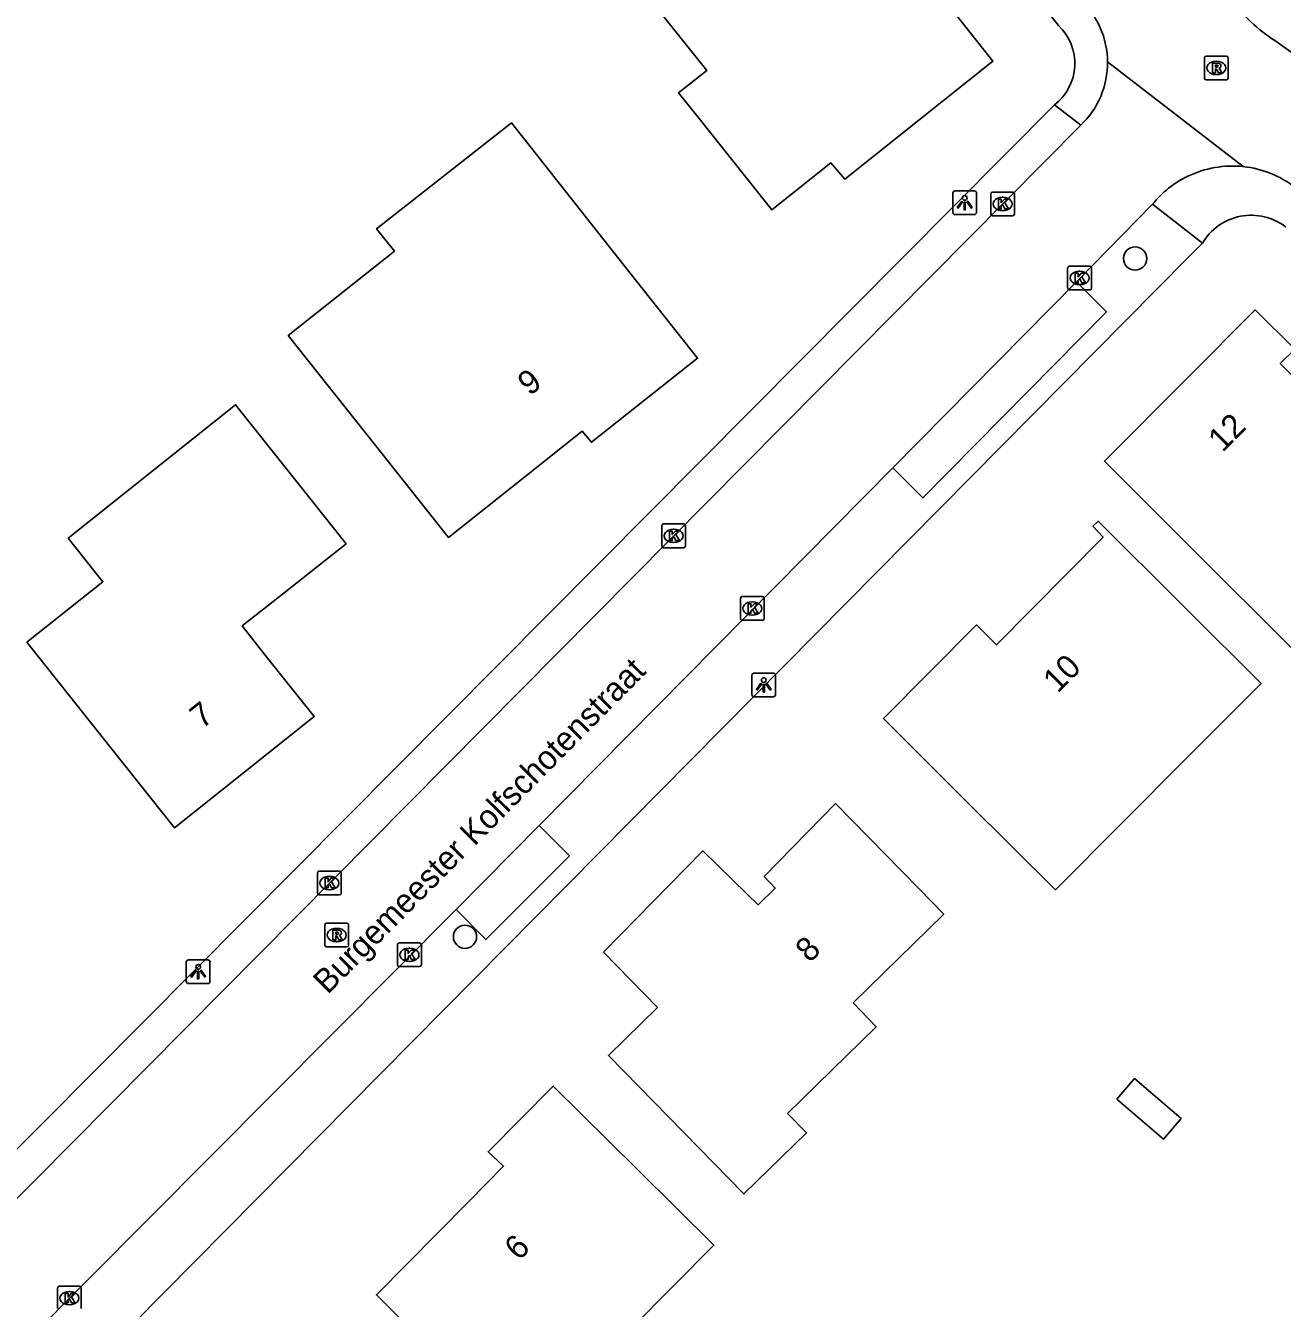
# Model space of a CAD drawing. Extents: x 159503 to 160347, y 382525 to 383272.
# Drawn here: x 159951.1 to 160004, y 383011.2 to 383065.2 of the extents above; entities that cross this region are included whole.
import ezdxf

# ---------------------------------------------------------------- set-up
doc = ezdxf.new("R2010")
doc.units = 0
for name, color, linetype in [('IMGEO_Boom', 7, 'Continuous'), ('IMGEO_Kolk', 7, 'Continuous'), ('IMGEO_Lichtpunt', 7, 'Continuous'), ('IMGEO_Openbare_ruimte_label', 7, 'Continuous'), ('IMGEO_Pand', 7, 'Continuous'), ('IMGEO_Pand_nummerreeks', 7, 'Continuous'), ('IMGEO_Rijbaan_lokaal_open', 7, 'Continuous'), ('IMGEO_Rioolput', 7, 'Continuous'), ('IMGEO_Voetpad_open', 7, 'Continuous')]:
    doc.layers.add(name, color=color, linetype=linetype)

msp = doc.modelspace()

# ---------------------------------------------------------------- linework, layer by layer
at = {"layer": 'IMGEO_Boom'}
for centre in [(159997.779, 383055.391), (159969.591, 383026.857)]:
    msp.add_circle(centre, 0.489, dxfattribs=at)
at = {"layer": 'IMGEO_Kolk'}
for p, q in [((159991.707, 383057.26), (159991.707, 383058.112)), ((159991.782, 383058.186), (159992.634, 383058.186)), ((159992.708, 383058.112), (159992.708, 383057.26)), ((159992.195, 383057.966), (159992.22, 383057.966)), ((159992.634, 383057.186), (159991.782, 383057.186)), ((159992.218, 383057.406), (159992.193, 383057.406)), ((159994.944, 383054.146), (159994.944, 383054.998)), ((159995.019, 383055.072), (159995.871, 383055.072)), ((159995.432, 383054.852), (159995.457, 383054.852)), ((159995.945, 383054.998), (159995.945, 383054.146)), ((159995.871, 383054.072), (159995.019, 383054.072)), ((159995.455, 383054.292), (159995.43, 383054.292)), ((159977.867, 383043.298), (159977.867, 383044.15)), ((159977.942, 383044.224), (159978.794, 383044.224)), ((159978.868, 383044.15), (159978.868, 383043.298)), ((159978.355, 383044.004), (159978.38, 383044.004)), ((159978.794, 383043.224), (159977.942, 383043.224)), ((159978.378, 383043.444), (159978.353, 383043.444)), ((159981.179, 383040.243), (159981.179, 383041.095)), ((159981.254, 383041.169), (159982.106, 383041.169)), ((159981.667, 383040.949), (159981.692, 383040.949)), ((159982.18, 383041.095), (159982.18, 383040.243)), ((159981.69, 383040.389), (159981.665, 383040.389)), ((159982.106, 383040.169), (159981.254, 383040.169)), ((159963.388, 383028.691), (159963.388, 383029.543)), ((159963.463, 383029.617), (159964.315, 383029.617)), ((159964.389, 383029.543), (159964.389, 383028.691)), ((159963.876, 383029.397), (159963.901, 383029.397)), ((159964.315, 383028.617), (159963.463, 383028.617)), ((159963.899, 383028.837), (159963.874, 383028.837)), ((159966.755, 383025.673), (159966.755, 383026.525)), ((159966.83, 383026.599), (159967.682, 383026.599)), ((159967.243, 383026.379), (159967.268, 383026.379)), ((159967.756, 383026.525), (159967.756, 383025.673)), ((159967.266, 383025.819), (159967.241, 383025.819)), ((159967.682, 383025.599), (159966.83, 383025.599)), ((159952.45, 383011.224), (159952.45, 383012.076)), ((159952.525, 383012.15), (159953.377, 383012.15)), ((159952.938, 383011.93), (159952.963, 383011.93)), ((159953.451, 383012.076), (159953.451, 383011.224)), ((159952.961, 383011.37), (159952.936, 383011.37))]:
    msp.add_line(p, q, dxfattribs=at)
for points in [[(159991.707, 383057.26), (159991.707, 383058.112)], [(159991.782, 383058.186), (159992.634, 383058.186)], [(159992.708, 383058.112), (159992.708, 383057.26)], [(159992.028, 383057.886), (159992.151, 383057.886), (159992.151, 383057.735), (159992.281, 383057.886), (159992.445, 383057.886), (159992.299, 383057.735), (159992.452, 383057.486), (159992.3, 383057.486), (159992.215, 383057.65), (159992.151, 383057.583), (159992.151, 383057.486), (159992.028, 383057.486), (159992.028, 383057.886)], [(159992.634, 383057.186), (159991.782, 383057.186)], [(159994.944, 383054.146), (159994.944, 383054.998)], [(159995.019, 383055.072), (159995.871, 383055.072)], [(159995.945, 383054.998), (159995.945, 383054.146)], [(159995.265, 383054.772), (159995.388, 383054.772), (159995.388, 383054.621), (159995.518, 383054.772), (159995.682, 383054.772), (159995.536, 383054.621), (159995.689, 383054.372), (159995.537, 383054.372), (159995.452, 383054.536), (159995.388, 383054.469), (159995.388, 383054.372), (159995.265, 383054.372), (159995.265, 383054.772)], [(159995.871, 383054.072), (159995.019, 383054.072)], [(159977.867, 383043.298), (159977.867, 383044.15)], [(159977.942, 383044.224), (159978.794, 383044.224)], [(159978.868, 383044.15), (159978.868, 383043.298)], [(159978.188, 383043.924), (159978.311, 383043.924), (159978.311, 383043.773), (159978.441, 383043.924), (159978.605, 383043.924), (159978.459, 383043.773), (159978.612, 383043.524), (159978.46, 383043.524), (159978.375, 383043.688), (159978.311, 383043.621), (159978.311, 383043.524), (159978.188, 383043.524), (159978.188, 383043.924)], [(159978.794, 383043.224), (159977.942, 383043.224)], [(159981.179, 383040.243), (159981.179, 383041.095)], [(159981.254, 383041.169), (159982.106, 383041.169)], [(159981.5, 383040.869), (159981.623, 383040.869), (159981.623, 383040.718), (159981.753, 383040.869), (159981.917, 383040.869), (159981.771, 383040.718), (159981.924, 383040.469), (159981.772, 383040.469), (159981.687, 383040.633), (159981.623, 383040.566), (159981.623, 383040.469), (159981.5, 383040.469), (159981.5, 383040.869)], [(159982.18, 383041.095), (159982.18, 383040.243)], [(159982.106, 383040.169), (159981.254, 383040.169)], [(159963.388, 383028.691), (159963.388, 383029.543)], [(159963.463, 383029.617), (159964.315, 383029.617)], [(159964.389, 383029.543), (159964.389, 383028.691)], [(159963.709, 383029.317), (159963.832, 383029.317), (159963.832, 383029.166), (159963.962, 383029.317), (159964.126, 383029.317), (159963.98, 383029.166), (159964.133, 383028.917), (159963.981, 383028.917), (159963.896, 383029.081), (159963.832, 383029.014), (159963.832, 383028.917), (159963.709, 383028.917), (159963.709, 383029.317)], [(159964.315, 383028.617), (159963.463, 383028.617)], [(159966.755, 383025.673), (159966.755, 383026.525)], [(159966.83, 383026.599), (159967.682, 383026.599)], [(159967.076, 383026.299), (159967.199, 383026.299), (159967.199, 383026.148), (159967.329, 383026.299), (159967.493, 383026.299), (159967.347, 383026.148), (159967.5, 383025.899), (159967.348, 383025.899), (159967.263, 383026.063), (159967.199, 383025.996), (159967.199, 383025.899), (159967.076, 383025.899), (159967.076, 383026.299)], [(159967.756, 383026.525), (159967.756, 383025.673)], [(159967.682, 383025.599), (159966.83, 383025.599)], [(159952.45, 383011.224), (159952.45, 383012.076)], [(159952.525, 383012.15), (159953.377, 383012.15)], [(159952.771, 383011.85), (159952.894, 383011.85), (159952.894, 383011.699), (159953.024, 383011.85), (159953.188, 383011.85), (159953.042, 383011.699), (159953.195, 383011.45), (159953.043, 383011.45), (159952.958, 383011.614), (159952.894, 383011.547), (159952.894, 383011.45), (159952.771, 383011.45), (159952.771, 383011.85)], [(159953.451, 383012.076), (159953.451, 383011.224)]]:
    msp.add_lwpolyline(points, dxfattribs=at)
for centre, start, end in [((159991.784, 383058.11), 91.552, 178.448), ((159991.784, 383058.11), 91.552, 178.448), ((159992.632, 383058.11), 1.552, 88.448), ((159992.632, 383058.11), 1.552, 88.448), ((159991.784, 383057.262), 181.552, 268.448), ((159991.784, 383057.262), 181.552, 268.448), ((159992.632, 383057.262), 271.552, 358.448), ((159992.632, 383057.262), 271.552, 358.448), ((159995.021, 383054.996), 91.552, 178.448), ((159995.021, 383054.996), 91.552, 178.448), ((159995.869, 383054.996), 1.552, 88.448), ((159995.869, 383054.996), 1.552, 88.448), ((159995.021, 383054.148), 181.552, 268.448), ((159995.021, 383054.148), 181.552, 268.448), ((159995.869, 383054.148), 271.552, 358.448), ((159995.869, 383054.148), 271.552, 358.448), ((159977.944, 383044.148), 91.552, 178.448), ((159977.944, 383044.148), 91.552, 178.448), ((159978.792, 383044.148), 1.552, 88.448), ((159978.792, 383044.148), 1.552, 88.448), ((159977.944, 383043.3), 181.552, 268.448), ((159977.944, 383043.3), 181.552, 268.448), ((159978.792, 383043.3), 271.552, 358.448), ((159978.792, 383043.3), 271.552, 358.448), ((159981.256, 383041.093), 91.552, 178.448), ((159981.256, 383041.093), 91.552, 178.448), ((159982.104, 383041.093), 1.552, 88.448), ((159982.104, 383041.093), 1.552, 88.448), ((159981.256, 383040.245), 181.552, 268.448), ((159981.256, 383040.245), 181.552, 268.448), ((159982.104, 383040.245), 271.552, 358.448), ((159982.104, 383040.245), 271.552, 358.448), ((159963.465, 383029.541), 91.552, 178.448), ((159963.465, 383029.541), 91.552, 178.448), ((159964.313, 383029.541), 1.552, 88.448), ((159964.313, 383029.541), 1.552, 88.448), ((159963.465, 383028.693), 181.552, 268.448), ((159963.465, 383028.693), 181.552, 268.448), ((159964.313, 383028.693), 271.552, 358.448), ((159964.313, 383028.693), 271.552, 358.448), ((159966.832, 383026.523), 91.552, 178.448), ((159966.832, 383026.523), 91.552, 178.448), ((159967.68, 383026.523), 1.552, 88.448), ((159967.68, 383026.523), 1.552, 88.448), ((159966.832, 383025.675), 181.552, 268.448), ((159966.832, 383025.675), 181.552, 268.448), ((159967.68, 383025.675), 271.552, 358.448), ((159967.68, 383025.675), 271.552, 358.448), ((159952.527, 383012.074), 91.552, 178.448), ((159952.527, 383012.074), 91.552, 178.448), ((159953.375, 383012.074), 1.552, 88.448), ((159953.375, 383012.074), 1.552, 88.448)]:
    msp.add_arc(centre, 0.0765, start, end, dxfattribs=at)
for centre, major_axis, ratio, start_param, end_param in [((159992.194, 383057.686), (-0.387, 0.002), 0.722429, 4.712389, 7.853982), ((159992.219, 383057.686), (-0.39, 0.002), 0.717154, 1.570796, 4.712389), ((159995.431, 383054.572), (-0.387, 0.002), 0.722429, 4.712389, 7.853982), ((159995.456, 383054.572), (-0.39, 0.002), 0.717154, 1.570796, 4.712389), ((159978.354, 383043.724), (-0.387, 0.002), 0.722429, 4.712389, 7.853982), ((159978.379, 383043.724), (-0.39, 0.002), 0.717154, 1.570796, 4.712389), ((159981.666, 383040.669), (-0.387, 0.002), 0.722429, 4.712389, 7.853982), ((159981.691, 383040.669), (-0.39, 0.002), 0.717154, 1.570796, 4.712389), ((159963.875, 383029.117), (-0.387, 0.002), 0.722429, 4.712389, 7.853982), ((159963.9, 383029.117), (-0.39, 0.002), 0.717154, 1.570796, 4.712389), ((159967.242, 383026.099), (-0.387, 0.002), 0.722429, 4.712389, 7.853982), ((159967.267, 383026.099), (-0.39, 0.002), 0.717154, 1.570796, 4.712389), ((159952.937, 383011.65), (-0.387, 0.002), 0.722429, 4.712389, 7.853982), ((159952.962, 383011.65), (-0.39, 0.002), 0.717154, 1.570796, 4.712389)]:
    msp.add_ellipse(centre, major_axis=major_axis, ratio=ratio, start_param=start_param, end_param=end_param, dxfattribs=at)
at = {"layer": 'IMGEO_Lichtpunt'}
for p, q in [((159990.114, 383058.14), (159990.114, 383057.333)), ((159990.114, 383058.14), (159990.114, 383057.333)), ((159991.016, 383058.235), (159990.208, 383058.235)), ((159991.016, 383058.235), (159990.208, 383058.235)), ((159991.11, 383057.333), (159991.11, 383058.14)), ((159991.11, 383057.333), (159991.11, 383058.14)), ((159990.208, 383057.239), (159991.016, 383057.239)), ((159990.208, 383057.239), (159991.016, 383057.239)), ((159981.663, 383037.858), (159981.663, 383037.051)), ((159981.663, 383037.858), (159981.663, 383037.051)), ((159982.565, 383037.953), (159981.757, 383037.953)), ((159982.565, 383037.953), (159981.757, 383037.953)), ((159982.659, 383037.051), (159982.659, 383037.858)), ((159982.659, 383037.051), (159982.659, 383037.858)), ((159981.757, 383036.957), (159982.565, 383036.957)), ((159981.757, 383036.957), (159982.565, 383036.957)), ((159957.869, 383025.789), (159957.869, 383024.982)), ((159957.869, 383025.789), (159957.869, 383024.982)), ((159958.771, 383025.884), (159957.963, 383025.884)), ((159958.771, 383025.884), (159957.963, 383025.884)), ((159958.865, 383024.982), (159958.865, 383025.789)), ((159958.865, 383024.982), (159958.865, 383025.789)), ((159957.963, 383024.888), (159958.771, 383024.888)), ((159957.963, 383024.888), (159958.771, 383024.888))]:
    msp.add_line(p, q, dxfattribs=at)
for points in [[(159990.488, 383057.804), (159990.527, 383057.776), (159990.339, 383057.514), (159990.301, 383057.541), (159990.488, 383057.804)], [(159990.59, 383057.756), (159990.637, 383057.756), (159990.637, 383057.434), (159990.59, 383057.434), (159990.59, 383057.756)], [(159990.7, 383057.776), (159990.738, 383057.803), (159990.925, 383057.541), (159990.886, 383057.513), (159990.7, 383057.776)], [(159982.037, 383037.522), (159982.076, 383037.494), (159981.888, 383037.232), (159981.85, 383037.259), (159982.037, 383037.522)], [(159982.139, 383037.474), (159982.186, 383037.474), (159982.186, 383037.152), (159982.139, 383037.152), (159982.139, 383037.474)], [(159982.249, 383037.494), (159982.287, 383037.521), (159982.474, 383037.259), (159982.435, 383037.231), (159982.249, 383037.494)], [(159958.243, 383025.453), (159958.282, 383025.425), (159958.094, 383025.163), (159958.056, 383025.19), (159958.243, 383025.453)], [(159958.345, 383025.405), (159958.392, 383025.405), (159958.392, 383025.083), (159958.345, 383025.083), (159958.345, 383025.405)], [(159958.455, 383025.425), (159958.493, 383025.452), (159958.68, 383025.19), (159958.641, 383025.162), (159958.455, 383025.425)]]:
    msp.add_lwpolyline(points, dxfattribs=at)
for centre in [(159990.613, 383057.938), (159982.162, 383037.656), (159958.368, 383025.587)]:
    msp.add_circle(centre, 0.0994, dxfattribs=at)
for centre, start, end in [((159990.208, 383058.14), 90, 180), ((159990.208, 383058.14), 90, 180), ((159991.016, 383058.14), 0, 90), ((159991.016, 383058.14), 0, 90), ((159990.208, 383057.333), 180, 270), ((159990.208, 383057.333), 180, 270), ((159991.016, 383057.333), 270, 0), ((159991.016, 383057.333), 270, 360), ((159981.757, 383037.858), 90, 180), ((159981.757, 383037.858), 90, 180), ((159982.565, 383037.858), 0, 90), ((159982.565, 383037.858), 0, 90), ((159981.757, 383037.051), 180, 270), ((159981.757, 383037.051), 180, 270), ((159982.565, 383037.051), 270, 0), ((159982.565, 383037.051), 270, 360), ((159957.963, 383025.789), 90, 180), ((159957.963, 383025.789), 90, 180), ((159958.771, 383025.789), 0, 90), ((159958.771, 383025.789), 0, 90), ((159957.963, 383024.982), 180, 270), ((159957.963, 383024.982), 180, 270), ((159958.771, 383024.982), 270, 0), ((159958.771, 383024.982), 270, 360)]:
    msp.add_arc(centre, 0.0946, start, end, dxfattribs=at)
at = {"layer": 'IMGEO_Pand'}
for points in [[(159981.882, 383076.202), (159991.799, 383063.691), (159985.573, 383058.726), (159984.982, 383059.41), (159982.494, 383057.437), (159979.38, 383061.349), (159978.579, 383062.354), (159979.762, 383063.296), (159976.547, 383067.334), (159977.876, 383068.392), (159975.603, 383071.247), (159977.958, 383073.105), (159981.882, 383076.202)], [(159971.548, 383061.092), (159976.275, 383055.117), (159979.378, 383051.196), (159974.913, 383047.661), (159974.524, 383048.121), (159972.105, 383046.202), (159968.896, 383043.657), (159965.789, 383047.575), (159962.16, 383052.15), (159966.626, 383055.693), (159965.875, 383056.641), (159971.548, 383061.092)], [(160022.835, 383043.344), (160020.072, 383040.329), (160019.964, 383040.406), (160017.822, 383038.215), (160011.897, 383042.713), (160010.015, 383044.143), (160009.617, 383043.744), (160007.725, 383041.846), (160006.635, 383040.752), (160004.632, 383038.743), (160000, 383043.36), (159996.487, 383046.861), (160000, 383050.386), (160002.833, 383053.227), (160004.499, 383051.579), (160003.888, 383050.973), (160005.247, 383049.625), (160005.857, 383050.259), (160010.742, 383045.406), (160014.563, 383049.24)], [(159961.478, 383047.306), (159964.591, 383043.393), (159961.909, 383041.272), (159960.215, 383039.932), (159961.289, 383038.584), (159963.253, 383036.118), (159957.377, 383031.434), (159954.264, 383035.346), (159951.162, 383039.244), (159954.363, 383041.791), (159952.9, 383043.63), (159959.943, 383049.235), (159961.478, 383047.306)], [(159990.736, 383032.51), (159987.194, 383036.039), (159991.106, 383039.978), (159991.952, 383039.134), (159996.431, 383043.666), (159996.003, 383044.132), (159996.229, 383044.338), (159999.771, 383040.809), (160000, 383040.58), (160003.079, 383037.51), (160000, 383034.422), (159994.427, 383028.831), (159990.736, 383032.51)], [(159985.914, 383024.07), (159986.893, 383023.066), (159983.163, 383019.421), (159983.958, 383018.607), (159981.327, 383016.035), (159975.626, 383021.867), (159977.688, 383023.883), (159975.416, 383026.208), (159979.6, 383030.469), (159981.453, 383028.661), (159981.925, 383028.201), (159982.645, 383028.906), (159982.178, 383029.394), (159985.183, 383032.461), (159988.677, 383028.884), (159989.734, 383027.803), (159985.914, 383024.07)], [(159997.014, 383020.021), (159997.755, 383020.887), (159999.717, 383019.208), (159998.976, 383018.342), (159997.014, 383020.021)], [(159974.891, 383008.662), (159975.996, 383004.592), (159972.853, 383001.418), (159967.057, 383007.206), (159967.262, 383007.411), (159967.418, 383007.256), (159968.909, 383008.749), (159965.866, 383011.787), (159969.736, 383015.708), (159971.215, 383017.206), (159970.564, 383017.814), (159973.308, 383020.573), (159976.861, 383017.055), (159980.062, 383013.885), (159974.891, 383008.662)]]:
    msp.add_lwpolyline(points, dxfattribs=at)
at = {"layer": 'IMGEO_Rijbaan_lokaal_open'}
for points in [[(159994.564, 383065.187), (159980.466, 383082.767)], [(160003.656, 383064.565), (160009.676, 383060.27)], [(159996.624, 383063.658), (160002.332, 383059.256)], [(159923.721, 382990.801), (159932.922, 383000), (159934.742, 383001.82), (159994.392, 383061.861)], [(159994.392, 383061.861), (159995.495, 383061.001)], [(159995.495, 383061.001), (159935.774, 383000.752), (159935.074, 383000), (159925.512, 382990.469)], [(159995.318, 383054.41), (159998.515, 383057.675)], [(159987.584, 383046.582), (159995.318, 383054.41)], [(159972.715, 383031.539), (159987.584, 383046.582)], [(159969.218, 383028.009), (159972.715, 383031.539)], [(159951.133, 383009.814), (159969.218, 383028.009)]]:
    msp.add_lwpolyline(points, dxfattribs=at)
for centre, radius, start, end in [((159992.986, 383063.631), 3.638, 0.4181, 47.1521), ((160006.929, 383069.78), 6.157, 214.1587, 237.8896), ((159993.064, 383063.597), 2.186, 307.4057, 46.6736), ((159992.992, 383063.633), 3.632, 313.5639, 0.3933), ((160001.879, 383054.939), 4.341, 84.0099, 115.6471), ((160001.877, 383054.948), 4.332, 52.2681, 83.9672), ((160001.887, 383054.946), 4.338, 115.7857, 141.0145)]:
    msp.add_arc(centre, radius, start, end, dxfattribs=at)
at = {"layer": 'IMGEO_Rioolput'}
for p, q in [((160000.697, 383062.982), (160000.697, 383063.834)), ((160000.772, 383063.908), (160001.624, 383063.908)), ((160001.185, 383063.688), (160001.21, 383063.688)), ((160001.698, 383063.834), (160001.698, 383062.982)), ((160001.208, 383063.128), (160001.183, 383063.128)), ((160001.624, 383062.908), (160000.772, 383062.908)), ((159963.696, 383026.504), (159963.696, 383027.356)), ((159963.771, 383027.43), (159964.623, 383027.43)), ((159964.697, 383027.356), (159964.697, 383026.504)), ((159964.184, 383027.21), (159964.209, 383027.21)), ((159964.623, 383026.43), (159963.771, 383026.43)), ((159964.207, 383026.65), (159964.182, 383026.65))]:
    msp.add_line(p, q, dxfattribs=at)
for points in [[(160000.697, 383062.982), (160000.697, 383063.834)], [(160000.772, 383063.908), (160001.624, 383063.908)], [(160001.286, 383063.606), (160001.034, 383063.608), (160001.034, 383063.208)], [(160001.212, 383063.527), (160001.158, 383063.527), (160001.158, 383063.446)], [(160001.698, 383063.834), (160001.698, 383062.982)], [(160001.034, 383063.208), (160001.158, 383063.208), (160001.158, 383063.37), (160001.169, 383063.37)], [(160001.158, 383063.446), (160001.21, 383063.446)], [(160001.216, 383063.341), (160001.287, 383063.208), (160001.427, 383063.208), (160001.362, 383063.334)], [(160001.624, 383062.908), (160000.772, 383062.908)], [(159963.696, 383026.504), (159963.696, 383027.356)], [(159963.771, 383027.43), (159964.623, 383027.43)], [(159964.697, 383027.356), (159964.697, 383026.504)], [(159964.285, 383027.128), (159964.033, 383027.13), (159964.033, 383026.73)], [(159964.033, 383026.73), (159964.157, 383026.73), (159964.157, 383026.892), (159964.168, 383026.892)], [(159964.211, 383027.049), (159964.157, 383027.049), (159964.157, 383026.968)], [(159964.157, 383026.968), (159964.209, 383026.968)], [(159964.215, 383026.863), (159964.286, 383026.73), (159964.426, 383026.73), (159964.361, 383026.856)], [(159964.623, 383026.43), (159963.771, 383026.43)]]:
    msp.add_lwpolyline(points, dxfattribs=at)
for centre, radius, start, end in [((160000.774, 383063.832), 0.0765, 91.552, 178.448), ((160000.774, 383063.832), 0.0765, 91.552, 178.448), ((160001.218, 383063.431), 0.0964, 77.0061, 93.1865), ((160001.232, 383063.488), 0.0378, 276.6634, 79.6772), ((160001.285, 383063.496), 0.109, 350.3612, 89.416), ((160001.283, 383063.496), 0.112, 277.5842, 350.9817), ((160001.622, 383063.832), 0.0765, 1.552, 88.448), ((160001.622, 383063.832), 0.0765, 1.552, 88.448), ((160000.774, 383062.984), 0.0765, 181.552, 268.448), ((160000.774, 383062.984), 0.0765, 181.552, 268.448), ((160001.168, 383063.317), 0.0533, 26.0293, 88.6989), ((160001.194, 383063.635), 0.19, 274.7715, 282.9687), ((160001.267, 383063.281), 0.108, 29.5134, 73.7905), ((160001.622, 383062.984), 0.0765, 271.552, 358.448), ((160001.622, 383062.984), 0.0765, 271.552, 358.448), ((159963.773, 383027.354), 0.0765, 91.552, 178.448), ((159963.773, 383027.354), 0.0765, 91.552, 178.448), ((159964.621, 383027.354), 0.0765, 1.552, 88.448), ((159964.621, 383027.354), 0.0765, 1.552, 88.448), ((159964.167, 383026.839), 0.0533, 26.0293, 88.6989), ((159964.193, 383027.157), 0.19, 274.7715, 282.9687), ((159964.217, 383026.953), 0.0964, 77.0061, 93.1865), ((159964.231, 383027.01), 0.0378, 276.6634, 79.6772), ((159964.284, 383027.018), 0.109, 350.3612, 89.416), ((159964.282, 383027.018), 0.112, 277.5842, 350.9817), ((159964.266, 383026.803), 0.108, 29.5134, 73.7905), ((159963.773, 383026.506), 0.0765, 181.552, 268.448), ((159963.773, 383026.506), 0.0765, 181.552, 268.448), ((159964.621, 383026.506), 0.0765, 271.552, 358.448), ((159964.621, 383026.506), 0.0765, 271.552, 358.448)]:
    msp.add_arc(centre, radius, start, end, dxfattribs=at)
for centre, major_axis, ratio, start_param, end_param in [((160001.184, 383063.408), (-0.387, 0.002), 0.722429, 4.712389, 7.853982), ((160001.209, 383063.408), (-0.39, 0.002), 0.717154, 1.570796, 4.712389), ((159964.183, 383026.93), (-0.387, 0.002), 0.722429, 4.712389, 7.853982), ((159964.208, 383026.93), (-0.39, 0.002), 0.717154, 1.570796, 4.712389)]:
    msp.add_ellipse(centre, major_axis=major_axis, ratio=ratio, start_param=start_param, end_param=end_param, dxfattribs=at)
at = {"layer": 'IMGEO_Voetpad_open'}
for points in [[(159998.515, 383057.675), (160000.612, 383056.034)], [(160000.612, 383056.034), (160000, 383055.416), (159945.155, 383000), (159941.372, 382996.178), (159937.839, 382992.604)], [(159995.318, 383054.41), (159996.578, 383053.144), (159988.858, 383045.317), (159987.584, 383046.582)], [(159972.715, 383031.539), (159973.983, 383030.267), (159970.468, 383026.739), (159969.218, 383028.009)]]:
    msp.add_lwpolyline(points, dxfattribs=at)
msp.add_arc((160002.667, 383054.832), 2.38, 52.3124, 149.6789, dxfattribs=at)

# ---------------------------------------------------------------- texts
at = {"layer": 'IMGEO_Openbare_ruimte_label'}
msp.add_text('Burgemeester Kolfschotenstraat', height=1, rotation=45.2834, dxfattribs=at).set_placement((159963.817, 383024.404))
at = {"layer": 'IMGEO_Pand_nummerreeks'}
for s, rotation, p in [('9', 38.4206, (159972.315, 383049.586)), ('12', 45.0918, (160001.462, 383047.206)), ('10', 45.337, (159994.524, 383037.069)), ('7', 38.5598, (159958.528, 383035.575)), ('8', 44.3985, (159984.09, 383025.73)), ('6', 45.3725, (159971.865, 383013.195))]:
    msp.add_text(s, height=1, rotation=rotation, dxfattribs=at).set_placement(p)

doc.saveas('drawing.dxf')
